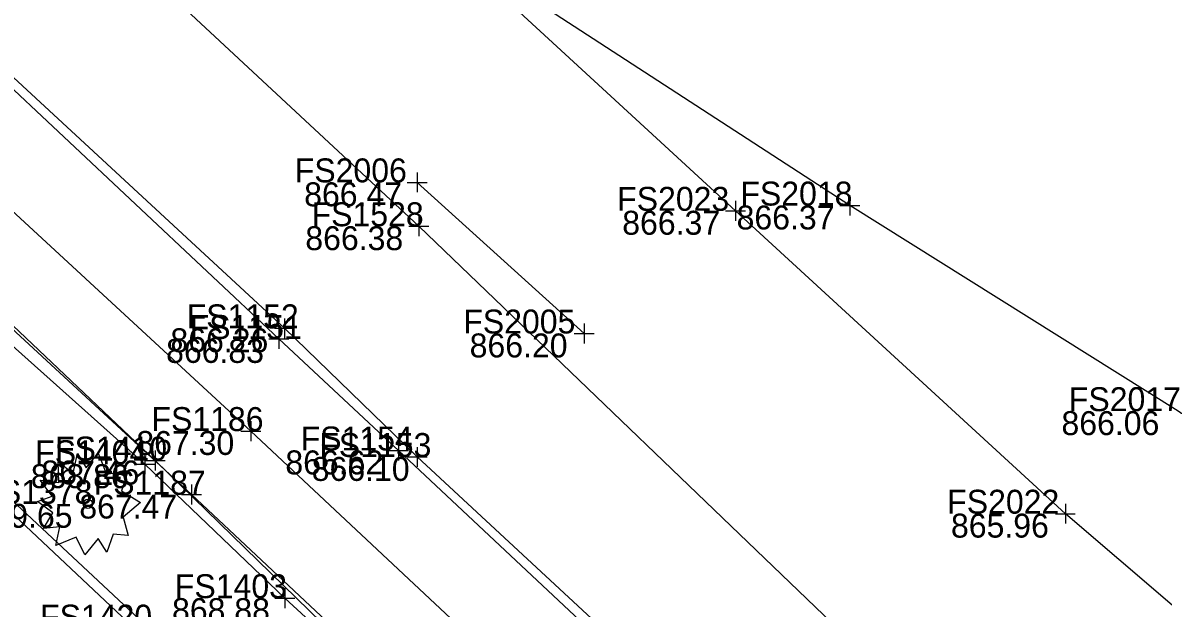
# Model space of a CAD drawing. Extents: x 1479420 to 1479833, y 379731 to 380103.
# Drawn here: x 1479710.9 to 1479768.1, y 379790.7 to 379820.1 of the extents above; entities that cross this region are included whole.
import ezdxf

# ---------------------------------------------------------------- set-up
doc = ezdxf.new("R2010")
doc.units = 0
for name, color, linetype in [('PM_X_CL_Double_Solid', 7, 'Continuous'), ('PM_X_Lane_Line', 7, 'Continuous'), ('PV_X_Curb', 7, 'Continuous'), ('PV_X_Walk', 7, 'Continuous'), ('RD_X_Wall', 7, 'Continuous'), ('SV_X_Break_Lines', 7, 'Continuous'), ('SV_X_Shot_Marker', 7, 'Continuous'), ('SV_X_Text_Elevation', 7, 'Continuous'), ('SV_X_Text_Name', 7, 'Continuous'), ('UT_X_Water', 7, 'Continuous'), ('VG_X_Cells', 7, 'Continuous')]:
    doc.layers.add(name, color=color, linetype=linetype)

msp = doc.modelspace()

# ---------------------------------------------------------------- linework, layer by layer
at = {"layer": 'PM_X_CL_Double_Solid'}
for points in [[(1479794.219, 379768.772), (1479779.093, 379781.771), (1479763.159, 379795.427), (1479746.619, 379810.624), (1479732.239, 379823.873), (1479714.719, 379840.653), (1479700.713, 379853.615), (1479677.934, 379875.066)], [(1479803.529, 379770.896), (1479781.948, 379790.708), (1479777.891, 379794.074), (1479768.812, 379800.571), (1479752.353, 379810.888), (1479732.762, 379823.628)]]:
    msp.add_lwpolyline(points, dxfattribs=at)
at = {"layer": 'PM_X_Lane_Line'}
msp.add_line((1479739.036, 379804.468), (1479730.662, 379812.052), dxfattribs=at)
at = {"layer": 'PV_X_Curb'}
for points in [[(1479752.341, 379756.82), (1479734.895, 379773.493), (1479717.229, 379789.662), (1479699.298, 379806.401), (1479688.16, 379794.934), (1479685.526, 379793.897), (1479682.733, 379795.157), (1479681.263, 379797.549), (1479682.493, 379800.746), (1479693.462, 379811.911), (1479675.554, 379828.75), (1479655.832, 379847.057), (1479640.191, 379861.808), (1479628.558, 379849), (1479624.614, 379847.663), (1479622.46, 379848.585), (1479618.996, 379850.857), (1479611.825, 379854.437), (1479601.319, 379856.891), (1479590.521, 379858.038)], [(1479751.933, 379756.628), (1479734.447, 379772.976), (1479716.701, 379789.463), (1479699.4, 379805.742), (1479688.561, 379794.786), (1479685.717, 379793.294), (1479682.291, 379794.8), (1479680.73, 379797.254), (1479682.169, 379801.189), (1479692.652, 379811.907), (1479675.183, 379828.391), (1479655.51, 379846.682), (1479640.151, 379860.926), (1479629.134, 379848.869), (1479624.571, 379847.215), (1479622.228, 379847.911), (1479618.757, 379850.398), (1479611.519, 379853.97), (1479601.347, 379856.369), (1479590.364, 379857.442)], [(1479667.529, 379857.521), (1479681.356, 379844.557), (1479695.384, 379831.416), (1479709.512, 379818.131), (1479724.003, 379804.728), (1479730.662, 379798.272), (1479750.68, 379779.69), (1479759.253, 379771.893), (1479760.555, 379770.78), (1479775.03, 379758.526), (1479788.183, 379747.585), (1479800.537, 379737.251), (1479801.677, 379736.292)], [(1479667.239, 379857.122), (1479681.024, 379844.208), (1479695.135, 379830.978), (1479709.331, 379817.708), (1479723.729, 379804.193), (1479729.719, 379798.6), (1479748.963, 379780.548), (1479759.065, 379771.485), (1479760.185, 379770.473), (1479774.837, 379758.13), (1479787.835, 379747.16), (1479799.962, 379737.109), (1479801.3, 379736.045)]]:
    msp.add_lwpolyline(points, dxfattribs=at)
at = {"layer": 'PV_X_Walk'}
for points in [[(1479760.141, 379765.373), (1479756.862, 379768.221), (1479747.096, 379776.51), (1479736.047, 379786.698), (1479722.324, 379799.574), (1479705.728, 379814.894), (1479685.769, 379833.708), (1479660.411, 379857.395)], [(1479801.031, 379735.954), (1479794.804, 379736.123), (1479792.191, 379733.142), (1479782.769, 379741.06), (1479767.055, 379754.294), (1479759.061, 379761.026), (1479757.309, 379762.481), (1479754.256, 379765.105), (1479744.261, 379773.561), (1479732.859, 379783.688), (1479719.35, 379796.384), (1479703.027, 379811.462), (1479682.443, 379830.686), (1479657.296, 379854.468)]]:
    msp.add_lwpolyline(points, dxfattribs=at)
at = {"layer": 'RD_X_Wall'}
msp.add_lwpolyline([(1479756.217, 379756.164), (1479757.574, 379758.774), (1479757.809, 379760.44), (1479756.184, 379761.773), (1479753.461, 379764.22), (1479749.272, 379767.89), (1479743.159, 379773.169), (1479734.585, 379781.475), (1479724.018, 379791.188), (1479717.004, 379797.909), (1479704.341, 379809.227)], dxfattribs=at)
at = {"layer": 'SV_X_Break_Lines'}
msp.add_lwpolyline([(1479700.791, 379810.474), (1479703.421, 379811.158), (1479704.398, 379810.048), (1479708.429, 379806.713), (1479717.526, 379798.095), (1479729.107, 379786.809), (1479738.375, 379778.753), (1479747.99, 379770.392), (1479758.225, 379761.836), (1479757.039, 379755.523)], dxfattribs=at)
at = {"layer": 'SV_X_Shot_Marker'}
for p, q in [((1479730.662, 379812.552), (1479730.662, 379811.552)), ((1479730.162, 379812.052), (1479731.162, 379812.052)), ((1479730.662, 379812.052), (1479730.662, 379812.052)), ((1479746.619, 379811.124), (1479746.619, 379810.124)), ((1479752.353, 379811.388), (1479752.353, 379810.388)), ((1479746.119, 379810.624), (1479747.119, 379810.624)), ((1479746.619, 379810.624), (1479746.619, 379810.624)), ((1479751.853, 379810.888), (1479752.853, 379810.888)), ((1479752.353, 379810.888), (1479752.353, 379810.888)), ((1479730.739, 379810.35), (1479730.739, 379809.35)), ((1479730.239, 379809.85), (1479731.239, 379809.85)), ((1479730.739, 379809.85), (1479730.739, 379809.85)), ((1479724.003, 379805.228), (1479724.003, 379804.228)), ((1479739.036, 379804.968), (1479739.036, 379803.968)), ((1479723.503, 379804.728), (1479724.503, 379804.728)), ((1479723.729, 379804.693), (1479723.729, 379803.693)), ((1479724.003, 379804.728), (1479724.003, 379804.728)), ((1479738.536, 379804.468), (1479739.536, 379804.468)), ((1479739.036, 379804.468), (1479739.036, 379804.468)), ((1479723.229, 379804.193), (1479724.229, 379804.193)), ((1479723.729, 379804.193), (1479723.729, 379804.193)), ((1479722.324, 379800.074), (1479722.324, 379799.074)), ((1479721.824, 379799.574), (1479722.824, 379799.574)), ((1479722.324, 379799.574), (1479722.324, 379799.574)), ((1479729.719, 379799.1), (1479729.719, 379798.1)), ((1479717.526, 379798.595), (1479717.526, 379797.595)), ((1479729.219, 379798.6), (1479730.219, 379798.6)), ((1479729.719, 379798.6), (1479729.719, 379798.6)), ((1479730.662, 379798.772), (1479730.662, 379797.772)), ((1479717.004, 379798.409), (1479717.004, 379797.409)), ((1479717.026, 379798.095), (1479718.026, 379798.095)), ((1479717.526, 379798.095), (1479717.526, 379798.095)), ((1479730.162, 379798.272), (1479731.162, 379798.272)), ((1479730.662, 379798.272), (1479730.662, 379798.272)), ((1479716.504, 379797.909), (1479717.504, 379797.909)), ((1479717.004, 379797.909), (1479717.004, 379797.909)), ((1479719.35, 379796.884), (1479719.35, 379795.884)), ((1479718.85, 379796.384), (1479719.85, 379796.384)), ((1479719.35, 379796.384), (1479719.35, 379796.384)), ((1479763.159, 379795.927), (1479763.159, 379794.927)), ((1479762.659, 379795.427), (1479763.659, 379795.427)), ((1479763.159, 379795.427), (1479763.159, 379795.427)), ((1479724.018, 379791.688), (1479724.018, 379790.688)), ((1479723.518, 379791.188), (1479724.518, 379791.188)), ((1479724.018, 379791.188), (1479724.018, 379791.188))]:
    msp.add_line(p, q, dxfattribs=at)
at = {"layer": 'UT_X_Water'}
msp.add_lwpolyline([(1479473.217, 380054.881), (1479498.741, 380029.974), (1479514.505, 380014.086), (1479533.448, 379996.735), (1479556.003, 379974.319), (1479574.861, 379956.271), (1479584.403, 379947.432), (1479599.597, 379932.819), (1479630.106, 379903.783), (1479644.769, 379889.722), (1479654.209, 379882.356), (1479664.266, 379872.629), (1479692.509, 379845.847), (1479712.672, 379826.686), (1479730.739, 379809.85), (1479753.15, 379788.309), (1479771.842, 379770.542), (1479781.678, 379761.101)], dxfattribs=at)
at = {"layer": 'VG_X_Cells'}
msp.add_lwpolyline([(1479714.064, 379797.731), (1479714.669, 379798.466), (1479715.084, 379797.413), (1479716.176, 379797.593), (1479715.837, 379796.581), (1479716.782, 379795.986), (1479715.926, 379795.251), (1479716.176, 379794.338), (1479715.422, 379794.406), (1479715.097, 379793.493), (1479714.669, 379794.185), (1479713.991, 379793.368), (1479713.562, 379794.255), (1479712.542, 379793.825), (1479712.734, 379794.766), (1479711.922, 379794.683), (1479712.396, 379795.473), (1479711.627, 379796.041), (1479712.366, 379796.305), (1479711.759, 379797.108), (1479712.691, 379796.998), (1479712.661, 379798.036), (1479713.414, 379797.468), (1479713.621, 379798.453), (1479714.064, 379797.731)], dxfattribs=at)
msp.add_circle((1479714.148, 379795.922), 0.23, dxfattribs=at)

# ---------------------------------------------------------------- texts
at = {"layer": 'SV_X_Text_Elevation'}
for s, p in [('866.47', (1479724.993, 379810.852)), ('866.37', (1479740.941, 379809.424)), ('866.37', (1479746.675, 379809.688)), ('866.38', (1479725.051, 379808.65)), ('866.26', (1479718.287, 379803.528)), ('866.20', (1479733.291, 379803.268)), ('866.83', (1479718.07, 379802.993)), ('866.06', (1479762.964, 379799.371)), ('867.30', (1479716.579, 379798.374)), ('866.62', (1479724.05, 379797.4)), ('867.46', (1479711.819, 379796.895)), ('866.10', (1479725.372, 379797.072)), ('868.86', (1479711.288, 379796.709)), ('867.47', (1479713.719, 379795.184)), ('869.65', (1479708.471, 379794.721)), ('865.96', (1479757.424, 379794.227)), ('868.88', (1479718.368, 379789.988))]:
    msp.add_text(s, height=1.2, dxfattribs=at).set_placement(p)
at = {"layer": 'SV_X_Text_Name'}
for s, p in [('FS2006', (1479724.521, 379812.052)), ('FS2023', (1479740.686, 379810.624)), ('FS2018', (1479746.864, 379810.888)), ('FS1528', (1479725.364, 379809.85)), ('FS1152', (1479719.101, 379804.728)), ('FS1151', (1479719.251, 379804.193)), ('FS2005', (1479732.97, 379804.468)), ('FS2017', (1479763.333, 379800.571)), ('FS1186', (1479717.337, 379799.574)), ('FS1154', (1479724.817, 379798.6)), ('FS1404', (1479711.506, 379797.909)), ('FS1410', (1479712.501, 379798.095)), ('FS1153', (1479725.75, 379798.272)), ('FS1187', (1479714.438, 379796.384)), ('FS1378', (1479708.755, 379795.921)), ('FS2022', (1479757.235, 379795.427)), ('FS1403', (1479718.51, 379791.188)), ('FS1420', (1479711.75, 379789.662))]:
    msp.add_text(s, height=1.2, dxfattribs=at).set_placement(p)

doc.saveas('drawing.dxf')
